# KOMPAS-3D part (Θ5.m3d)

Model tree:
1. Эскиз:1
2. Операция выдавливания:1
     Расстояние 1 = 2
3. Скругление:1
     Радиус = 2
4. Эскиз:2
5. Вырезать элемент выдавливания:1
     Расстояние 1 = 10
